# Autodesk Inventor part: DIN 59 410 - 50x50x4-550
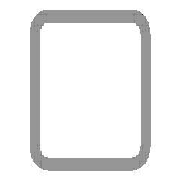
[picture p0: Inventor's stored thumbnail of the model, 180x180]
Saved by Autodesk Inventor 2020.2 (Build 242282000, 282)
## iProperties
Manager: www.cadconsulting.pl
Company: Fabian Stasiak CAD Consulting
Created: 2015-01
Part Number: DIN 59 410 - 50x50x4-550
Material: Stal, miękka
Description: Rurki stalowe o przekroju kwadratowym formowane na gorąco
Document SubType Name: Modellieren
Standard: DIN
Designer: F.Stasiak
Standards Organization: DIN
Language: pl-PL
Size Designation: 50x50x4
Categories: <MemberInstance><Categories><Category DisplayName="Kształtowniki konstrukcyjne" InternalName="089c4875-fa83-4c05-b084-43b9cc11f5ed" Mnemonic="GRDR"><CategoryPar
Stock Number: 50x50x4
Density: 7.85 g/cm^3
Appearance: Częściowo polerowana
Mass: 2999.78 g
Surface Area: 1924.59 cm^2
Volume: 382.138 cm^3
Catalog Web Link: www.expertbooks.pl
_CCFamilyMember: 40
_CCFamilyDisplayName: DIN 59410 (Kwadrat) - Rurki stalowe o przekroju kwadratowym formowane na gorąco
_FrameMemberDoc: Frame Member File
_Version: 15.0.0
_GetPNFromCC: 1
G_W: 50,000 mm
G_H: 50,000 mm
+1173B185-85AD-4C83-AFDB-ED40A6D39A43+CUTDETAIL1: Wytnij
+96CA9664-CB53-4865-820D-545E97C69E15+CUTDETAIL2: Wytnij
G_L: 550,000 mm
IsCustomPart: 1
Author: F.Stasiak
Subject: Zbiór ćwiczeń. Autodesk Inventor 2020. Kurs Professional
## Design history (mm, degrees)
node "Płaszczyzna początkowa"
node "Płaszczyzna końcowa"
sketch "Szkic"
  geometry: L1 (-17, 25)-(17, 25); L2 (25, 17)-(25, -17); L3 (17, -25)-(-17, -25); L4 (-25, -17)-(-25, 17); L5 (-37.32, 0)-(37.32, 0) reference; L6 (0, -37.32)-(0, 37.32) reference; L7 (-17, 21)-(17, 21); L8 (21, 17)-(21, -17); L9 (17, -21)-(-17, -21); L10 (-21, -17)-(-21, 17); A1 r 8 centre (-17, 17) between (-17, 25) and (-25, 17); A2 r 8 centre (17, 17) between (25, 17) and (17, 25); A3 r 8 centre (17, -17) between (17, -25) and (25, -17); A4 r 8 centre (-17, -17) between (-25, -17) and (-17, -25); A5 r 4 centre (-17, 17) between (-17, 21) and (-21, 17); A6 r 4 centre (17, 17) between (21, 17) and (17, 21); A7 r 4 centre (17, -17) between (17, -21) and (21, -17); A8 r 4 centre (-17, -17) between (-21, -17) and (-17, -21); 3 further points
  constraints: 16 end point, 16 point on circle, 8 centre point, 8 tangent, 6 point on line, 4 parallel, 3 equal radius, 3 perpendicular, 1 horizontal, 7 other
  dimensions: "b" = 50 distance of point (-25, 25) point (25, 25); "msp_r" = 8 radius of A1 (= 2 x ParT); "d8" = 25 distance between parallel lines of L4 L6 (= d9); "d9" = 25 distance between parallel lines of L3 L5 (= 0.5 x b); "d10" = 4 distance between parallel lines of L3 L9 (= ParT)
extrude "Bryła" new body sketch "Szkic" taper "d4" = 0 deg; stored distance "NLG" = 10
node "Driven Length"
  sketch "Sketch2"
    geometry: L1 (0, 0)-(10, 0) reference
    constraints: 2 end point, 1 horizontal
  workplane "Work Plane3"
  sketch "Sketch3"
    geometry: L1 (-2, 25)-(12, 25) reference; L2 (-2, 575)-(12, 575) reference
    dimensions: "d14" = 550 distance between parallel lines of L1 L2 (derived)
node "Płaszczyzna konstrukcyjna4"
feature "Podział1"
node "Płaszczyzna konstrukcyjna5"
feature "Podział2"
body "Solid1"
other parameters: "ParT" = 4, "G_OFFSET_START" = -25 [user parameter; used in 1 equation term], "G_OFFSET_END" = -25 [user parameter; used in 1 equation term], "d11" = 25 (= -G_OFFSET_START), "d12" = 575 (= G_OFFSET_END + B_L), "G_L" = 550 (= d14) [user parameter], "d13" = 90 deg
